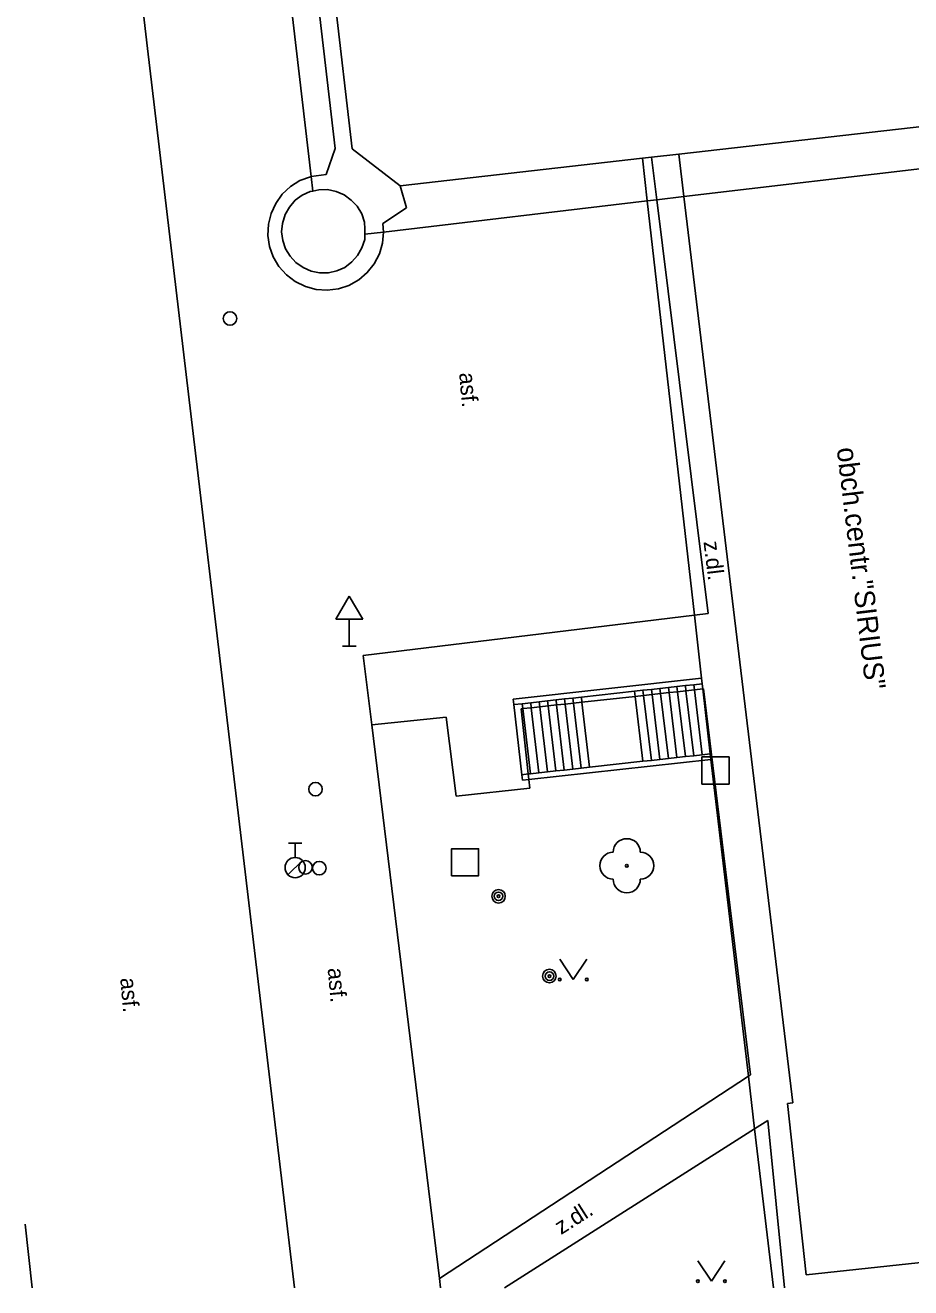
# Model space of a CAD drawing. Extents: x -642282 to -641982, y -1041678 to -1041427.
# Drawn here: x -642170.13 to -642137.39, y -1041678.03 to -1041631.36 of the extents above; entities that cross this region are included whole.
import ezdxf

# ---------------------------------------------------------------- set-up
doc = ezdxf.new("R2010")
doc.units = 0
for name, color, linetype in [('Budovy', 7, 'Continuous'), ('Popis objektů', 7, 'Continuous'), ('Popis povrchů', 7, 'Continuous'), ('Rozhraní ploch 1', 7, 'Continuous'), ('Rozhraní ploch 2', 7, 'Continuous'), ('Sloupy_označník', 7, 'Continuous'), ('Zeleň - stromy', 7, 'Continuous'), ('Znaky voda', 7, 'Continuous'), ('Značky doprava', 7, 'Continuous'), ('Značky KM', 7, 'Continuous'), ('Šachty ner_', 7, 'Continuous')]:
    doc.layers.add(name, color=color, linetype=linetype)

msp = doc.modelspace()

# ---------------------------------------------------------------- linework, layer by layer
at = {"layer": 'Budovy'}
for p, q in [((-642159.562, -1041636.949), (-642162.898, -1041608.407)), ((-642158.04, -1041635.93), (-642161.18, -1041609.06)), ((-642145.97, -1041636.12), (-642128.97, -1041634.19)), ((-642145.781, -1041637.695), (-642127.79, -1041635.57)), ((-642156.27, -1041637.29), (-642158.04, -1041635.93)), ((-642147.312, -1041636.272), (-642156.27, -1041637.29)), ((-642146.974, -1041636.234), (-642147.312, -1041636.272)), ((-642147.133, -1041637.854), (-642147.312, -1041636.272)), ((-642145.97, -1041636.12), (-642146.974, -1041636.234)), ((-642145.781, -1041637.695), (-642145.97, -1041636.12)), ((-642159.499, -1041637.489), (-642159.562, -1041636.949)), ((-642160.15, -1041637.83), (-642159.89, -1041637.64)), ((-642159.89, -1041637.64), (-642159.59, -1041637.51)), ((-642159.59, -1041637.51), (-642159.499, -1041637.489)), ((-642159.499, -1041637.489), (-642159.28, -1041637.44)), ((-642159.28, -1041637.44), (-642158.95, -1041637.43)), ((-642158.95, -1041637.43), (-642158.64, -1041637.5)), ((-642158.64, -1041637.5), (-642158.34, -1041637.63)), ((-642158.34, -1041637.63), (-642158.08, -1041637.82)), ((-642146.778, -1041637.813), (-642145.781, -1041637.695)), ((-642141.75, -1041671.2), (-642145.781, -1041637.695)), ((-642160.52, -1041638.36), (-642160.36, -1041638.08)), ((-642160.36, -1041638.08), (-642160.15, -1041637.83)), ((-642158.08, -1041637.82), (-642157.86, -1041638.05)), ((-642157.86, -1041638.05), (-642157.69, -1041638.33)), ((-642156.885, -1041639.006), (-642147.133, -1041637.854)), ((-642147.133, -1041637.854), (-642146.778, -1041637.813)), ((-642145.388, -1041653.162), (-642147.133, -1041637.854)), ((-642160.65, -1041638.99), (-642160.62, -1041638.69)), ((-642160.62, -1041638.69), (-642160.52, -1041638.36)), ((-642157.69, -1041638.33), (-642157.59, -1041638.64)), ((-642157.59, -1041638.64), (-642157.57, -1041638.89)), ((-642160.61, -1041639.31), (-642160.65, -1041638.99)), ((-642157.571, -1041639.087), (-642157.58, -1041639.28)), ((-642157.57, -1041638.89), (-642157.571, -1041639.087)), ((-642157.571, -1041639.087), (-642156.885, -1041639.006)), ((-642160.51, -1041639.62), (-642160.61, -1041639.31)), ((-642160.34, -1041639.9), (-642160.51, -1041639.62)), ((-642157.68, -1041639.59), (-642157.84, -1041639.87)), ((-642157.58, -1041639.28), (-642157.68, -1041639.59)), ((-642160.12, -1041640.13), (-642160.34, -1041639.9)), ((-642157.84, -1041639.87), (-642158.05, -1041640.11)), ((-642159.86, -1041640.32), (-642160.12, -1041640.13)), ((-642159.56, -1041640.45), (-642159.86, -1041640.32)), ((-642159.25, -1041640.51), (-642159.56, -1041640.45)), ((-642158.92, -1041640.51), (-642159.25, -1041640.51)), ((-642158.61, -1041640.44), (-642158.92, -1041640.51)), ((-642158.31, -1041640.31), (-642158.61, -1041640.44)), ((-642158.05, -1041640.11), (-642158.31, -1041640.31)), ((-642145.122, -1041655.5), (-642145.388, -1041653.162)), ((-642145.099, -1041655.703), (-642145.122, -1041655.5)), ((-642145.077, -1041655.893), (-642145.099, -1041655.703)), ((-642144.803, -1041658.295), (-642145.077, -1041655.893)), ((-642144.78, -1041658.5), (-642144.803, -1041658.295)), ((-642143.394, -1041670.208), (-642144.78, -1041658.5)), ((-642143.164, -1041672.155), (-642143.394, -1041670.208)), ((-642141.75, -1041671.2), (-642141.95, -1041671.22)), ((-642141.26, -1041677.56), (-642141.95, -1041671.22)), ((-642142.468, -1041678.032), (-642143.164, -1041672.155)), ((-642134.88, -1041676.87), (-642141.26, -1041677.56))]:
    msp.add_line(p, q, dxfattribs=at)
at = {"layer": 'Rozhraní ploch 1'}
for p, q in [((-642165.61, -1041632.22), (-642168.245, -1041609.882)), ((-642165.61, -1041632.22), (-642161.09, -1041670.34)), ((-642143.321, -1041670.16), (-642145.05, -1041655.89)), ((-642154.81, -1041677.69), (-642157.31, -1041657.22)), ((-642151.478, -1041659.562), (-642154.2, -1041659.86)), ((-642151.513, -1041659.244), (-642151.478, -1041659.562)), ((-642161.09, -1041670.34), (-642160.176, -1041678.032)), ((-642154.81, -1041677.69), (-642143.394, -1041670.208)), ((-642143.394, -1041670.208), (-642143.321, -1041670.16)), ((-642143.164, -1041672.155), (-642152.406, -1041678.032)), ((-642142.68, -1041671.85), (-642143.164, -1041672.155)), ((-642142.055, -1041678.032), (-642142.68, -1041671.85)), ((-642169.879, -1041678.032), (-642170.138, -1041675.683))]:
    msp.add_line(p, q, dxfattribs=at)
for points in [[(-642151.8, -1041656.63), (-642151.733, -1041656.623), (-642151.42, -1041656.589), (-642151.107, -1041656.555), (-642150.795, -1041656.521), (-642150.483, -1041656.487), (-642150.17, -1041656.453), (-642149.858, -1041656.419), (-642149.546, -1041656.385), (-642147.582, -1041656.169), (-642147.269, -1041656.135), (-642146.955, -1041656.1), (-642146.642, -1041656.066), (-642146.329, -1041656.031), (-642146.015, -1041655.996), (-642145.701, -1041655.962), (-642145.387, -1041655.927), (-642145.077, -1041655.893), (-642145.05, -1041655.89)], [(-642151.8, -1041656.63), (-642151.536, -1041659.039), (-642151.513, -1041659.244)], [(-642157.31, -1041657.22), (-642154.57, -1041656.94), (-642154.2, -1041659.86)]]:
    msp.add_lwpolyline(points, dxfattribs=at)
at = {"layer": 'Rozhraní ploch 2'}
for p, q in [((-642158.67, -1041635.91), (-642161.82, -1041608.93)), ((-642159.01, -1041636.88), (-642158.67, -1041635.91)), ((-642146.778, -1041637.813), (-642146.974, -1041636.234)), ((-642159.562, -1041636.949), (-642159.01, -1041636.88)), ((-642156.27, -1041637.29), (-642156.04, -1041638.11)), ((-642156.04, -1041638.11), (-642156.91, -1041638.69)), ((-642144.88, -1041653.1), (-642146.778, -1041637.813)), ((-642156.885, -1041639.006), (-642156.91, -1041638.69)), ((-642145.388, -1041653.162), (-642144.88, -1041653.1)), ((-642157.64, -1041654.66), (-642145.388, -1041653.162)), ((-642157.31, -1041657.22), (-642157.64, -1041654.66)), ((-642152.09, -1041656.27), (-642145.122, -1041655.5)), ((-642152.09, -1041656.27), (-642152.067, -1041656.473)), ((-642149.568, -1041656.197), (-642147.605, -1041655.98)), ((-642151.773, -1041659.065), (-642152.067, -1041656.473)), ((-642151.513, -1041659.244), (-642144.78, -1041658.5)), ((-642147.292, -1041658.57), (-642149.263, -1041658.788)), ((-642151.75, -1041659.27), (-642151.773, -1041659.065)), ((-642151.75, -1041659.27), (-642151.513, -1041659.244)), ((-642154.773, -1041678.032), (-642154.81, -1041677.69))]:
    msp.add_line(p, q, dxfattribs=at)
for points in [[(-642156.885, -1041639.006), (-642156.922, -1041639.417), (-642157.038, -1041639.814), (-642157.229, -1041640.18), (-642157.486, -1041640.504), (-642157.8, -1041640.771), (-642158.16, -1041640.974), (-642158.553, -1041641.103), (-642158.962, -1041641.154), (-642159.375, -1041641.126), (-642159.773, -1041641.019), (-642160.144, -1041640.837), (-642160.473, -1041640.587), (-642160.748, -1041640.279), (-642160.959, -1041639.924), (-642161.097, -1041639.534), (-642161.157, -1041639.126), (-642161.138, -1041638.713), (-642161.04, -1041638.312), (-642160.87, -1041637.95), (-642160.625, -1041637.602), (-642160.323, -1041637.321), (-642159.972, -1041637.102), (-642159.586, -1041636.956), (-642159.562, -1041636.949)], [(-642147.605, -1041655.98), (-642147.292, -1041655.945), (-642146.978, -1041655.91), (-642146.665, -1041655.876), (-642146.352, -1041655.841), (-642146.038, -1041655.806), (-642145.724, -1041655.772), (-642145.41, -1041655.737), (-642145.099, -1041655.703)], [(-642147.292, -1041655.945), (-642147.269, -1041656.135), (-642146.979, -1041658.535)], [(-642146.978, -1041655.91), (-642146.955, -1041656.1), (-642146.665, -1041658.5)], [(-642146.665, -1041655.876), (-642146.642, -1041656.066), (-642146.352, -1041658.466)], [(-642146.352, -1041655.841), (-642146.329, -1041656.031), (-642146.039, -1041658.431)], [(-642146.038, -1041655.806), (-642146.015, -1041655.996), (-642145.725, -1041658.396)], [(-642145.724, -1041655.772), (-642145.701, -1041655.962), (-642145.411, -1041658.362)], [(-642145.41, -1041655.737), (-642145.387, -1041655.927), (-642145.097, -1041658.327)], [(-642152.067, -1041656.473), (-642151.755, -1041656.439), (-642151.442, -1041656.404), (-642151.129, -1041656.369), (-642150.817, -1041656.335), (-642150.505, -1041656.301), (-642150.192, -1041656.266), (-642149.88, -1041656.232), (-642149.568, -1041656.197)], [(-642151.442, -1041656.404), (-642151.42, -1041656.589), (-642151.138, -1041658.995)], [(-642151.129, -1041656.369), (-642151.107, -1041656.555), (-642150.824, -1041658.96)], [(-642150.817, -1041656.335), (-642150.795, -1041656.521), (-642150.512, -1041658.926)], [(-642150.505, -1041656.301), (-642150.483, -1041656.487), (-642150.2, -1041658.892)], [(-642150.192, -1041656.266), (-642150.17, -1041656.453), (-642149.887, -1041658.857)], [(-642149.88, -1041656.232), (-642149.858, -1041656.419), (-642149.575, -1041658.823)], [(-642149.568, -1041656.197), (-642149.546, -1041656.385), (-642149.263, -1041658.788)], [(-642147.605, -1041655.98), (-642147.582, -1041656.169), (-642147.292, -1041658.57)], [(-642151.755, -1041656.439), (-642151.733, -1041656.623), (-642151.45, -1041659.029)], [(-642147.292, -1041658.57), (-642146.979, -1041658.535), (-642146.665, -1041658.5), (-642146.352, -1041658.466), (-642146.039, -1041658.431), (-642145.725, -1041658.396), (-642145.411, -1041658.362), (-642145.097, -1041658.327), (-642144.803, -1041658.295)], [(-642151.773, -1041659.065), (-642151.536, -1041659.039), (-642151.45, -1041659.029), (-642151.138, -1041658.995), (-642150.824, -1041658.96), (-642150.512, -1041658.926), (-642150.2, -1041658.892), (-642149.887, -1041658.857), (-642149.575, -1041658.823), (-642149.263, -1041658.788)]]:
    msp.add_lwpolyline(points, dxfattribs=at)
at = {"layer": 'Sloupy_označník'}
for centre, radius in [((-642152.63, -1041663.56), 0.25), ((-642152.63, -1041663.56), 0.158), ((-642152.63, -1041663.56), 0.05), ((-642150.75, -1041666.51), 0.25), ((-642150.75, -1041666.51), 0.158), ((-642150.75, -1041666.51), 0.05)]:
    msp.add_circle(centre, radius, dxfattribs=at)
at = {"layer": 'Zeleň - stromy'}
msp.add_circle((-642147.89, -1041662.43), 0.05, dxfattribs=at)
for centre, start, end in [((-642147.89, -1041661.93), 0, 180), ((-642148.39, -1041662.43), 90, 270), ((-642147.39, -1041662.43), 270, 90), ((-642147.89, -1041662.93), 180, 0)]:
    msp.add_arc(centre, 0.5, start, end, dxfattribs=at)
at = {"layer": 'Znaky voda'}
for p, q in [((-642160.4, -1041661.6), (-642159.9, -1041661.6)), ((-642160.15, -1041662.125), (-642160.15, -1041661.6)), ((-642160.415, -1041662.765), (-642159.885, -1041662.235))]:
    msp.add_line(p, q, dxfattribs=at)
for centre, radius in [((-642162.56, -1041642.2), 0.25), ((-642159.4, -1041659.6), 0.25), ((-642160.15, -1041662.5), 0.375), ((-642159.77, -1041662.49), 0.25), ((-642159.26, -1041662.52), 0.25)]:
    msp.add_circle(centre, radius, dxfattribs=at)
at = {"layer": 'Značky doprava'}
for p, q in [((-642158.65, -1041653.31), (-642158.15, -1041652.46)), ((-642158.15, -1041652.46), (-642157.65, -1041653.31)), ((-642158.65, -1041653.31), (-642157.65, -1041653.31)), ((-642158.15, -1041654.31), (-642158.15, -1041653.31)), ((-642158.4, -1041654.31), (-642157.9, -1041654.31))]:
    msp.add_line(p, q, dxfattribs=at)
at = {"layer": 'Značky KM'}
for p, q in [((-642150.37, -1041665.89), (-642149.87, -1041666.64)), ((-642149.87, -1041666.64), (-642149.37, -1041665.89)), ((-642145.26, -1041677.04), (-642144.76, -1041677.79)), ((-642144.76, -1041677.79), (-642144.26, -1041677.04))]:
    msp.add_line(p, q, dxfattribs=at)
for centre in [(-642150.37, -1041666.64), (-642149.37, -1041666.64), (-642145.26, -1041677.79), (-642144.26, -1041677.79)]:
    msp.add_circle(centre, 0.05, dxfattribs=at)
at = {"layer": 'Šachty ner_'}
for points in [[(-642145.11, -1041659.41), (-642144.11, -1041659.41), (-642144.11, -1041658.41), (-642145.11, -1041658.41)], [(-642154.37, -1041662.8), (-642153.37, -1041662.8), (-642153.37, -1041661.8), (-642154.37, -1041661.8)]]:
    msp.add_lwpolyline(points, close=True, dxfattribs=at)

# ---------------------------------------------------------------- texts
at = {"layer": 'Popis objektů'}
msp.add_text('obch.centr."SIRIUS"', height=0.75, rotation=276.8599, dxfattribs=at).set_placement((-642140.13, -1041647))
at = {"layer": 'Popis povrchů'}
for s, rotation, p in [('asf.', 275.0864, (-642154.09, -1041644.22)), ('z.dl.', 276.9085, (-642145.055, -1041650.453)), ('asf.', 275.0864, (-642166.619, -1041666.591)), ('asf.', 275.0864, (-642158.95, -1041666.225)), ('z.dl.', 32.4527, (-642150.32, -1041676.087))]:
    msp.add_text(s, height=0.6, rotation=rotation, dxfattribs=at).set_placement(p)

doc.saveas('drawing.dxf')
